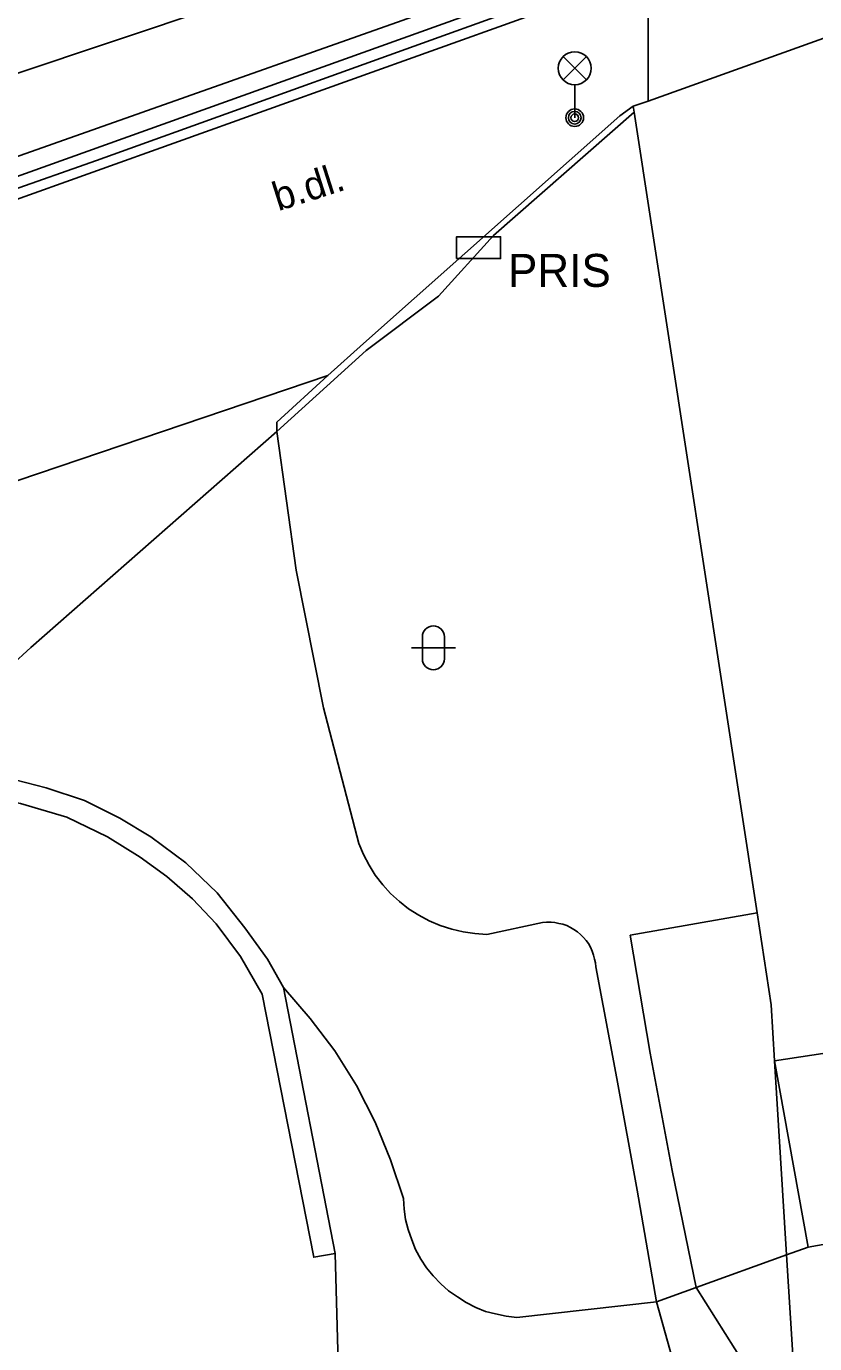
# Model space of a CAD drawing. Extents: x -596229 to -595156, y -1161237 to -1159376.
# Drawn here: x -595911.94 to -595894, y -1161198.03 to -1161168.04 of the extents above; entities that cross this region are included whole.
import ezdxf

# ---------------------------------------------------------------- set-up
doc = ezdxf.new("R2010")
doc.units = 0
for name, color, linetype in [('Level 24', 7, 'Continuous'), ('Level 33', 7, 'Continuous'), ('Level 36', 7, 'Continuous'), ('Specificka linie pasportu komunikaci', 7, 'Continuous'), ('TM - budovy zdene_ betonove - VP', 7, 'Continuous'), ('TM - komunikace - VP', 7, 'Continuous'), ('TM - letecke snimky - pomocna linie', 7, 'Continuous'), ('TM - plot drateny_ kovovy - VP', 7, 'Continuous'), ('TM - popis objektu', 7, 'Continuous'), ('TM - popis povrchu', 7, 'Continuous'), ('TM - rozhrani ploch obecne - VP', 7, 'Continuous'), ('TM - vjezd na pozemek', 7, 'Continuous'), ('TM - zabradli - VP', 7, 'Continuous'), ('TM - zed operna - VP', 7, 'Continuous')]:
    doc.layers.add(name, color=color, linetype=linetype)

msp = doc.modelspace()

# ---------------------------------------------------------------- linework, layer by layer
at = {"layer": 'Level 24'}
msp.add_lwpolyline([(-595902.147, -1161173.328), (-595901.147, -1161173.328), (-595901.147, -1161172.828), (-595902.147, -1161172.828)], close=True, dxfattribs=at)
at = {"layer": 'Level 33'}
for p, q in [((-595899.725, -1161169.26), (-595899.195, -1161168.73)), ((-595899.725, -1161168.73), (-595899.195, -1161169.26)), ((-595899.46, -1161169.37), (-595899.46, -1161170.12))]:
    msp.add_line(p, q, dxfattribs=at)
for centre, radius in [((-595899.46, -1161168.995), 0.375), ((-595899.46, -1161170.12), 0.2), ((-595899.46, -1161170.12), 0.145), ((-595899.46, -1161170.12), 0.0876)]:
    msp.add_circle(centre, radius, dxfattribs=at)
at = {"layer": 'Level 36'}
for p, q in [((-595902.926, -1161181.936), (-595902.926, -1161182.436)), ((-595902.426, -1161181.936), (-595902.426, -1161182.436)), ((-595903.176, -1161182.186), (-595902.176, -1161182.186))]:
    msp.add_line(p, q, dxfattribs=at)
for centre, start, end in [((-595902.676, -1161181.936), 0, 180), ((-595902.676, -1161182.436), 180, 0)]:
    msp.add_arc(centre, 0.25, start, end, dxfattribs=at)
at = {"layer": 'Specificka linie pasportu komunikaci'}
for points in [[(-595912.27, -1161169.15), (-595900.68, -1161165.27), (-595880.78, -1161158.55), (-595880.4, -1161158.42)], [(-595897.79, -1161169.74), (-595897.79, -1161166.83)], [(-595905.08, -1161175.99), (-595912.61, -1161178.54)]]:
    msp.add_lwpolyline(points, dxfattribs=at)
at = {"layer": 'TM - budovy zdene_ betonove - VP'}
for points in [[(-595897.79, -1161169.74), (-595881.55, -1161163.91)], [(-595898.13, -1161169.86), (-595897.79, -1161169.74)], [(-595898.11, -1161169.99), (-595898.13, -1161169.86)], [(-595895.31, -1161188.22), (-595898.11, -1161169.99)], [(-595894.99, -1161190.31), (-595895.31, -1161188.22)], [(-595894.91, -1161191.59), (-595894.99, -1161190.31)], [(-595894.91, -1161191.59), (-595888.42, -1161190.6)], [(-595894.15, -1161195.83), (-595894.91, -1161191.59)], [(-595887.79, -1161194.69), (-595894.15, -1161195.83)]]:
    msp.add_lwpolyline(points, dxfattribs=at)
at = {"layer": 'TM - komunikace - VP'}
msp.add_lwpolyline([(-595912.34, -1161171.07), (-595900.36, -1161166.83)], dxfattribs=at)
at = {"layer": 'TM - letecke snimky - pomocna linie'}
for points in [[(-595906.24, -1161177.26), (-595905.8, -1161180.42), (-595905.18, -1161183.55), (-595904.37, -1161186.64)], [(-595904.37, -1161186.64), (-595904.27, -1161186.89), (-595904.14, -1161187.13), (-595904, -1161187.36), (-595903.83, -1161187.58), (-595903.65, -1161187.78), (-595903.45, -1161187.96), (-595903.24, -1161188.13), (-595903.01, -1161188.27), (-595902.77, -1161188.4), (-595902.52, -1161188.51), (-595902.26, -1161188.59), (-595902, -1161188.65), (-595901.73, -1161188.69), (-595901.46, -1161188.71)], [(-595898.2, -1161188.73), (-595895.31, -1161188.22)], [(-595901.46, -1161188.71), (-595900.19, -1161188.44)], [(-595900.19, -1161188.44), (-595900.1, -1161188.43), (-595900, -1161188.43), (-595899.91, -1161188.44), (-595899.82, -1161188.46), (-595899.73, -1161188.48), (-595899.64, -1161188.51), (-595899.56, -1161188.55), (-595899.48, -1161188.6), (-595899.4, -1161188.65), (-595899.33, -1161188.71), (-595899.26, -1161188.78), (-595899.2, -1161188.85), (-595899.15, -1161188.92), (-595899.1, -1161189), (-595899.06, -1161189.09), (-595899.03, -1161189.18), (-595899.01, -1161189.27), (-595898.99, -1161189.36), (-595898.98, -1161189.45)], [(-595896.7, -1161196.75), (-595897.24, -1161194.08), (-595897.74, -1161191.41), (-595898.2, -1161188.73)], [(-595898.98, -1161189.45), (-595898.5, -1161191.99), (-595898.04, -1161194.53), (-595897.6, -1161197.07)], [(-595903.36, -1161194.72), (-595903.65, -1161193.84), (-595904, -1161192.98), (-595904.43, -1161192.15), (-595904.92, -1161191.36), (-595905.48, -1161190.62), (-595906.09, -1161189.92)], [(-595900.78, -1161197.43), (-595901.02, -1161197.4), (-595901.26, -1161197.35), (-595901.49, -1161197.29), (-595901.71, -1161197.2), (-595901.93, -1161197.09), (-595902.13, -1161196.96), (-595902.33, -1161196.82), (-595902.51, -1161196.66), (-595902.68, -1161196.48), (-595902.83, -1161196.3), (-595902.96, -1161196.1), (-595903.08, -1161195.88), (-595903.17, -1161195.66), (-595903.25, -1161195.43), (-595903.31, -1161195.2), (-595903.34, -1161194.96), (-595903.36, -1161194.72)], [(-595896.7, -1161196.75), (-595894.64, -1161196)], [(-595894.64, -1161196), (-595894.15, -1161195.83)], [(-595897.6, -1161197.07), (-595896.7, -1161196.75)], [(-595896.7, -1161196.75), (-595895.16, -1161199.19), (-595894.46, -1161198.89)], [(-595897.6, -1161197.07), (-595900.78, -1161197.43)], [(-595897.6, -1161197.07), (-595897.1, -1161198.86)]]:
    msp.add_lwpolyline(points, dxfattribs=at)
at = {"layer": 'TM - plot drateny_ kovovy - VP'}
for points in [[(-595898.11, -1161169.99), (-595901.31, -1161172.8)], [(-595901.31, -1161172.8), (-595902.56, -1161174.18)], [(-595904.21, -1161175.42), (-595906.24, -1161177.26)], [(-595911.84, -1161182.18), (-595906.24, -1161177.26)], [(-595912.77, -1161183.03), (-595911.84, -1161182.18)], [(-595894.64, -1161196), (-595894.91, -1161191.59)], [(-595903.829, -1161235.417), (-595904.91, -1161195.97)], [(-595894.46, -1161198.89), (-595894.64, -1161196)]]:
    msp.add_lwpolyline(points, dxfattribs=at)
at = {"layer": 'TM - rozhrani ploch obecne - VP'}
for points in [[(-595880.4, -1161160.13), (-595880.5, -1161160.16), (-595898.92, -1161166.71), (-595912.36, -1161171.53)], [(-595897.79, -1161166.83), (-595898.73, -1161167.16), (-595912.38, -1161172.06)], [(-595905.08, -1161175.99), (-595904.27, -1161175.26), (-595898.43, -1161170.08), (-595898.13, -1161169.86)], [(-595906.24, -1161177.26), (-595906.24, -1161177.05), (-595905.08, -1161175.99)]]:
    msp.add_lwpolyline(points, dxfattribs=at)
at = {"layer": 'TM - vjezd na pozemek'}
msp.add_lwpolyline([(-595902.56, -1161174.18), (-595904.21, -1161175.42)], dxfattribs=at)
at = {"layer": 'TM - zabradli - VP'}
msp.add_lwpolyline([(-595912.37, -1161171.81), (-595910.34, -1161171.09), (-595897.02, -1161166.29), (-595882.51, -1161161.14), (-595858.51, -1161152.82)], dxfattribs=at)
at = {"layer": 'TM - zed operna - VP'}
for points in [[(-595906.09, -1161189.92), (-595906.45, -1161189.27), (-595906.97, -1161188.56), (-595907.6, -1161187.76), (-595908.31, -1161187.08), (-595909.11, -1161186.49), (-595909.81, -1161186.06), (-595910.62, -1161185.66), (-595911.49, -1161185.37), (-595912.43, -1161185.13), (-595912.84, -1161185.09)], [(-595912.86, -1161185.58), (-595912.07, -1161185.73), (-595911.02, -1161186.04), (-595910.09, -1161186.49), (-595909.35, -1161186.95), (-595908.74, -1161187.39), (-595908.16, -1161187.9), (-595907.62, -1161188.47), (-595907.07, -1161189.21), (-595906.57, -1161190.07)], [(-595906.57, -1161190.07), (-595905.4, -1161196.06), (-595904.91, -1161195.97)], [(-595904.91, -1161195.97), (-595906.09, -1161189.92)]]:
    msp.add_lwpolyline(points, dxfattribs=at)

# ---------------------------------------------------------------- texts
at = {"layer": 'TM - popis objektu'}
msp.add_text('PRIS', height=0.75, dxfattribs=at).set_placement((-595900.98, -1161173.97))
at = {"layer": 'TM - popis povrchu'}
msp.add_text('b.dl.', height=0.65, rotation=17.6721, dxfattribs=at).set_placement((-595906.21, -1161172.25))

doc.saveas('drawing.dxf')
